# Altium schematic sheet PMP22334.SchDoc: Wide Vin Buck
size 431 x 279 mm; Date: Not shown in title block; ApprovedBy: Not shown in title block; CheckedBy: Not shown in title block; Author: Not shown in title block; CompanyName: Not shown in title block; DrawnBy: T Zhou; Engineer: Not shown in title block; Organization: Not shown in title block; Address1: Not shown in title block; Address2: Not shown in title block; Address3: Not shown in title block; Address4: Not shown in title block; DocumentNumber: 1; Revision: Use project parameter SCH_Rev; SheetNumber: 1; SheetTotal: 4; PageSetup: Record=PageOptions¦CenterHorizontal=True¦CenterVertical=True¦PrintScale=1.00¦XCorrection=1.00¦YCorrection=1.00¦PrintKind=0¦BorderSize=5000000¦LeftOffset=0¦BottomOffset=0¦Orientation=2¦PaperLength=1000¦PaperWidth=1000¦Scale=100¦PaperSource=15¦PrintQuality=600¦MediaType=1¦DitherType=10¦PaperKind=Letter¦PrintScaleMode=1
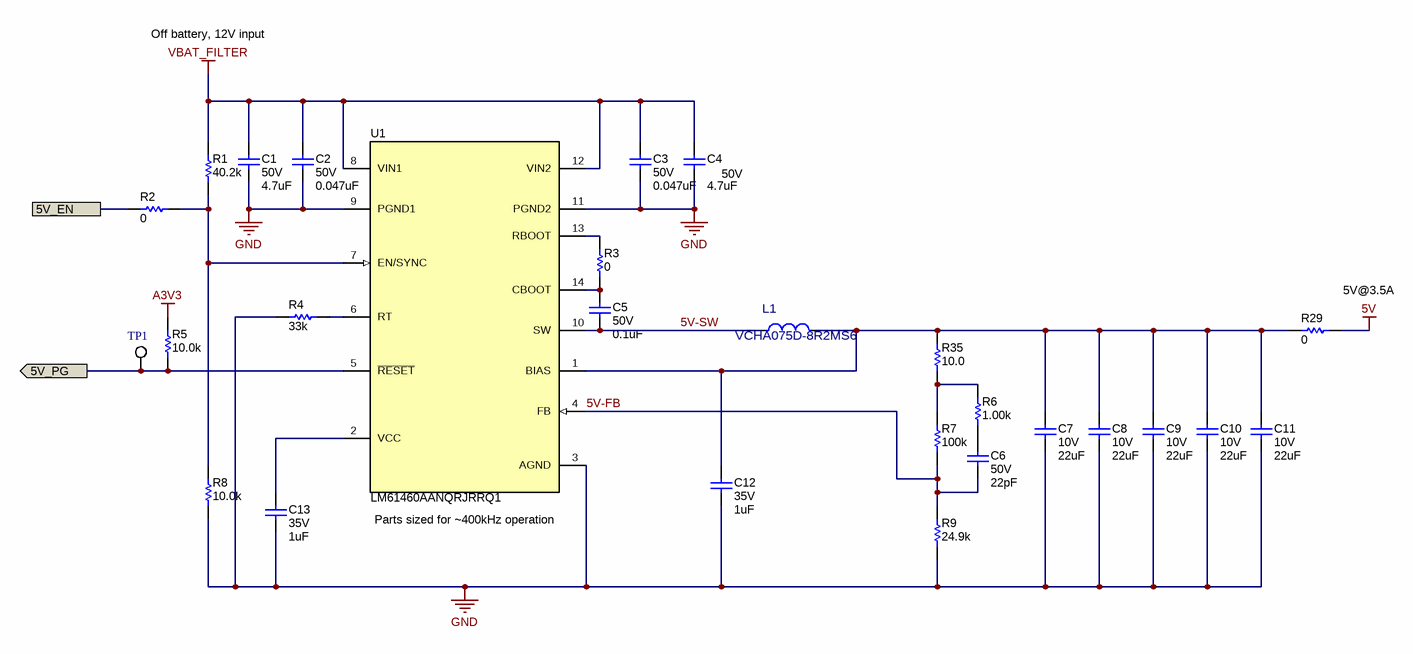
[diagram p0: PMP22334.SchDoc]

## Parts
C1  VDC_V: 50V  ValueDisplayed: 4.7uF  [1206_180]  (hidden comment: GRM31CR71H475KA12L)
C2  VDC_V: 50V  ValueDisplayed: 0.047uF  [0402S]  (hidden comment: CGA2B3X7R1H473K050BB)
C3  VDC_V: 50V  ValueDisplayed: 0.047uF  [0402S]  (hidden comment: CGA2B3X7R1H473K050BB)
C4  VDC_V: 50V  ValueDisplayed: 4.7uF  [1206_180]  (hidden comment: GRM31CR71H475KA12L)
C5  VDC_V: 50V  ValueDisplayed: 0.1uF  [0402S]  (hidden comment: CGA2B3X7R1H104K050BB)
C6  VDC_V: 50V  ValueDisplayed: 22pF  [0402S]  (hidden comment: C1005C0G1H220J050BA)
C7  VDC_V: 10V  ValueDisplayed: 22uF  [1206_180]  (hidden comment: GCM31CR71A226KE02)
C8  VDC_V: 10V  ValueDisplayed: 22uF  [1206_180]  (hidden comment: GCM31CR71A226KE02)
C9  VDC_V: 10V  ValueDisplayed: 22uF  [1206_180]  (hidden comment: GCM31CR71A226KE02)
C10  VDC_V: 10V  ValueDisplayed: 22uF  [1206_180]  (hidden comment: GCM31CR71A226KE02)
C11  VDC_V: 10V  ValueDisplayed: 22uF  [1206_180]  (hidden comment: GCM31CR71A226KE02)
C12  VDC_V: 35V  ValueDisplayed: 1uF  [0402S]  (hidden comment: GRM155R6YA105ME11D)
C13  VDC_V: 35V  ValueDisplayed: 1uF  [0402S]  (hidden comment: GRM155R6YA105ME11D)
L1  VCHA075D-8R2MS6  [FP-VCHA075D-8R2MS6_SMD-MFG]
R1  ValueDisplayed: 40.2k  [0402S]  (hidden comment: CRCW040240K2FKED)
R2  ValueDisplayed: 0  [0402S]  (hidden comment: CRCW04020000Z0ED)
R3  ValueDisplayed: 0  [0402S]  (hidden comment: CRCW04020000Z0ED)
R4  ValueDisplayed: 33k  [0402S]  (hidden comment: CRCW040233K0JNED)
R5  ValueDisplayed: 10.0k  [0402S]  (hidden comment: RMCF0402FT10K0)
R6  ValueDisplayed: 1.00k  [0402S]  (hidden comment: CRCW04021K00FKED)
R7  ValueDisplayed: 100k  [0402S]  (hidden comment: RC0402FR-07100KL)
R8  ValueDisplayed: 10.0k  [0402S]  (hidden comment: RMCF0402FT10K0)
R9  ValueDisplayed: 24.9k  [0402S]  (hidden comment: CRCW040224K9FKED)
R29  ValueDisplayed: 0  [2010]  (hidden comment: CRCW20100000Z0EF)
R35  ValueDisplayed: 10.0  [0402S]  (hidden comment: RMCF0402JT10R0)
TP1  5002  [Keystone5002]  (value not drawn)
U1  LM61460AANQRJRRQ1  [RJR0014A]

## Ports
5V_EN, 5V_PG (out)

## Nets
5V: R29.2
A3V3: R5.1
GND: C1.2 C2.2 C3.2 C4.2 C7.2 C8.2 C9.2 C10.2 C11.2 C12.2 C13.2 R4.2 R8.2 R9.1 U1.3(AGND) U1.9(PGND1) U1.11(PGND2)
VBAT_FILTER: C1.1 C2.1 C3.1 C4.1 R1.2 U1.8(VIN1) U1.12(VIN2)
5V-FB: C6.2 R7.1 R9.2 U1.4(FB)
5V-SW: C5.2 L1.1 U1.10(SW)
5V_EN: R2.1 ; port 5V_EN
5V_PG: R5.2 TP1.1 U1.5(~{RESET}) ; port 5V_PG
NetC5_1: C5.1 R3.2 U1.14(CBOOT)
NetC6_1: C6.1 R6.1
NetC7_1: C7.1 C8.1 C9.1 C10.1 C11.1 C12.1 L1.2 R29.1 R35.2 U1.1(BIAS)
NetC13_1: C13.1 U1.2(VCC)
NetR1_1: R1.1 R2.2 R8.1 U1.7(EN/SYNC)
NetR3_1: R3.1 U1.13(RBOOT)
NetR4_1: R4.1 U1.6(RT)
NetR6_2: R6.2 R7.2 R35.1

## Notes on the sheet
- Off battery, 12V input
- (near R29) 5V@3.5A
- (near U1) Parts sized for ~400kHz operation

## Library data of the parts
C1 C4 = CMP-0008969-2: CAP, CERM, 4.7 uF, 50 V, +/- 10%, X7R, 1206; Manufacturer: MuRata; TaMin_C: -55°C; Polarized: N; SizeAreaWB_mm2: 10.92; Value1: Unknown; U/M: EA; Value: 4.7uF; TaMax_C: 125°C; SizeZ_mm: 1.8; SizeX_mm: 3.2; SizeY_mm: 1.6; Cap_Case: 2220; SizeArea_mm2: 5.12; Cap_F: 4.7µF; AEC Category: Q200
C2 C3 = CMP-0006330-2: CAP, CERM, 0.047 uF, 50 V, +/- 10%, X7R, AEC-Q200 Grade 1, 0402; Manufacturer: TDK; TaMin_C: -55°C; Polarized: N; SizeAreaWB_mm2: 3; Value1: 0.06407 ohm; U/M: EA; TaMax_C: 125°C; SizeZ_mm: 0.6; SizeX_mm: 1; SizeY_mm: 0.5; Cap_Case: 0402; AEC Qualified: Y; Cap_F: 47nF; AEC Category: Q200; ESR_ohm: 0.06407; IRMS_A: 646.122mA
C5 = CMP-0006325-2: CAP, CERM, 0.1 uF, 50 V, +/- 10%, X7R, AEC-Q200 Grade 1, 0402; Manufacturer: TDK; TaMin_C: -55°C; Polarized: N; SizeAreaWB_mm2: 3; Value1: 0.039064 ohm; U/M: EA; Value: 0.1uF; TaMax_C: 125°C; SizeZ_mm: 0.6; SizeX_mm: 1; SizeY_mm: 0.5; Cap_Case: 0402; AEC Qualified: Y; Cap_F: 100nF; AEC Category: Q200; ESR_ohm: 0.039064; IRMS_A: 814.669mA
C6 = CMP-0006248-2: CAP, CERM, 22 pF, 50 V, +/- 5%, C0G/NP0, 0402; Manufacturer: TDK; TaMin_C: -55°C; Polarized: N; SizeAreaWB_mm2: 3; Value1: Unknown; U/M: EA; Value: 22pF; TaMax_C: 125°C; SizeZ_mm: 0.6; SizeX_mm: 1; SizeY_mm: 0.5; Cap_Case: 0402; AEC Category: Q200
C7-C11 = CMP-0008811-2: CAP, CERM, 22 uF, 10 V, +/- 10%, X7R, AEC-Q200 Grade 1, 1206; Manufacturer: MuRata; TaMin_C: -55°C; Polarized: N; SizeAreaWB_mm2: 10.92; Value1: Unknown; U/M: EA; Value: 22uF; TaMax_C: 125°C; SizeZ_mm: 1.8; SizeX_mm: 3.2; SizeY_mm: 1.6; Cap_Case: 1206; SizeArea_mm2: 5.12; AEC Qualified: Y; Cap_F: 22µF; AEC Grade: 1; AEC Category: Q200
C12 = CMP-0006620-2: CAP, CERM, 1 uF, 35 V, +/- 20%, X5R, 0402; Manufacturer: MuRata; TaMin_C: -55°C; Polarized: N; SizeAreaWB_mm2: 3; Value1: Unknown; U/M: EA; Value: 1uF; TaMax_C: 85°C; SizeZ_mm: 0.6; SizeX_mm: 1; SizeY_mm: 0.5; Cap_Case: 0402; Cap_F: 1µF; AEC Category: Q200
C13 = CMP-0006620-2: CAP, CERM, 1 uF, 35 V, +/- 20%, X5R, 0402; Manufacturer: MuRata; SizeZ_mm: 0.6; AEC Qualified: N; Cap_F: 1µF; TaMin_C: -55°C; SizeAreaWB_mm2: 3; Value1: Unknown; U/M: EA; Value: 1uF; TaMax_C: 85°C; SizeX_mm: 1; SizeY_mm: 0.5; Cap_Case: 0402; AEC Category: Q200
L1 = CMP-0089036-1: Power Choke Coil; Manufacturer: Cyntec; Isat: 9A; Irms: 5.6A; DCR_ohm: 0.0319; Material: Metal dust; SizeZ_mm: 5.4mm; Ind_H: 8.2µH; AEC Qualified: Yes; AEC Grade: Grade 0
R1 = CMP-0026367-2: RES, 40.2 k, 1%, 0.063 W, AEC-Q200 Grade 0, 0402; Manufacturer: Vishay-Dale; Power_W: 63mW; TempCo: 100 ppm/C; Value_Code: 40k2; Value: 40.2k; EIA_Code: E96; SizeX_mm: 1; SizeY_mm: 0.5; SizeZ_mm: 0.6; Value2: 0.063W; AEC Qualified: Y; VDC_V: 50V; AEC Grade: 0; AEC Category: Q200
R2 R3 = CMP-0026822-3: RES, 0, 5%, 0.063 W, AEC-Q200 Grade 0, 0402; Manufacturer: Vishay-Dale; Power_W: 63mW; TempCo: 200 ppm/C; Value_Code: 0000; Value: 0; EIA_Code: E24; SizeX_mm: 1; SizeY_mm: 0.5; SizeZ_mm: 0.6; Value2: 0.063W; AEC Qualified: Y; VDC_V: 50V; AEC Category: Q200
R4 = CMP-0026907-3: RES, 33 k, 5%, 0.063 W, AEC-Q200 Grade 0, 0402; Manufacturer: Vishay-Dale; Power_W: 63mW; TempCo: 200 ppm/C; Value_Code: 33k0; Value: 33k; EIA_Code: E24; SizeX_mm: 1; SizeY_mm: 0.5; SizeZ_mm: 0.6; Value2: 0.063W; AEC Qualified: Y; VDC_V: 50V; AEC Grade: 0; AEC Category: Q200
R5 R8 = CMP-0026754-1: RES, 10.0 k, 1%, 0.063 W, AEC-Q200 Grade 0, 0402; Manufacturer: Stackpole Electronics Inc; Power_W: 63mW; TempCo: 100 ppm/C; Value_Code: 10k0; U/M: EA; Value: 10.0k; EIA_Code: E96; Res_ohm: 10k; SizeX_mm: 1; SizeY_mm: 0.5; SizeZ_mm: 0.6; Value2: 0.063W; AEC Qualified: Y; VDC_V: 50V; AEC Grade: 0; AEC Category: Q200
R6 = CMP-0026071-3: RES, 1.00 k, 1%, 0.063 W, AEC-Q200 Grade 0, 0402; Manufacturer: Vishay-Dale; Power_W: 63mW; TempCo: 100 ppm/C; Value_Code: 1k00; Value: 1.00k; EIA_Code: E96; Res_ohm: 1k; SizeX_mm: 1; SizeY_mm: 0.5; SizeZ_mm: 0.6; Value2: 0.063W; AEC Qualified: Y; VDC_V: 50V; AEC Grade: 0; AEC Category: Q200
R7 = CMP-0026721-1: RES, 100 k, 1%, 0.0625 W, 0402; Manufacturer: Yageo America; Power_W: 62.5mW; TempCo: 100 ppm/C; U/M: EA; Value: 100k; EIA_Code: E96; SizeX_mm: 1; SizeY_mm: 0.5; SizeZ_mm: 0.6; AEC Qualified: N; VDC_V: 50V; AEC Category: Q200
R9 = CMP-0026196-2: RES, 24.9 k, 1%, 0.063 W, AEC-Q200 Grade 0, 0402; Manufacturer: Vishay-Dale; Power_W: 63mW; TempCo: 100 ppm/C; Value_Code: 24k9; Value: 24.9k; EIA_Code: E96; SizeX_mm: 1; SizeY_mm: 0.5; SizeZ_mm: 0.6; Value2: 0.063W; AEC Qualified: Y; VDC_V: 50V; AEC Grade: 0; AEC Category: Q200
R29 = CMP-0016044-3: RES, 0, 5%, 0.75 W, AEC-Q200 Grade 0, 2010; Manufacturer: Vishay-Dale; Power_W: 750mW; TempCo: ppm/C; Value_Code: 0000; Value: 0; EIA_Code: E24; SizeX_mm: 5; SizeY_mm: 2.5; SizeZ_mm: 1.66; Value2: 0.75W; SizeArea_mm2: 12.5; AEC Qualified: Y; AEC Category: Q200
R35 = CMP-0026764-1: RES, 10.0, 1%, 0.063 W, AEC-Q200 Grade 0, 0402; Manufacturer: Stackpole Electronics Inc; Power_W: 63mW; TempCo: 100 ppm/C; Value_Code: 10R0; Value: 10.0; EIA_Code: E96; Res_ohm: 10; SizeX_mm: 1; SizeY_mm: 0.5; SizeZ_mm: 0.6; Value2: 0.063W; AEC Qualified: Y; AEC Grade: 0; AEC Category: Q200; U/M: EA
TP1 = CMP-0055139-1: Test Point, Miniature, White, TH; Manufacturer: Keystone; CNHeader: FALSE; Green_Lifecycle: Active; Green_REACh: Passed; ContactFinish: Silver; CT: TRUE
U1 = CMP-0079827-1: Automotive 6-A Low Noise Synchronous Buck Regulators, RJR0014A (VQFN-HR-14); Alternate Manufacturer: Texas Instruments; SizeAreaWB_mm2: 22.5; SizeZ_mm: 1; SizeX_mm: 4; SizeY_mm: 3.5; SizeArea_mm2: 14; CompType: IC; AEC Qualified: Y; AEC Category: Q200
